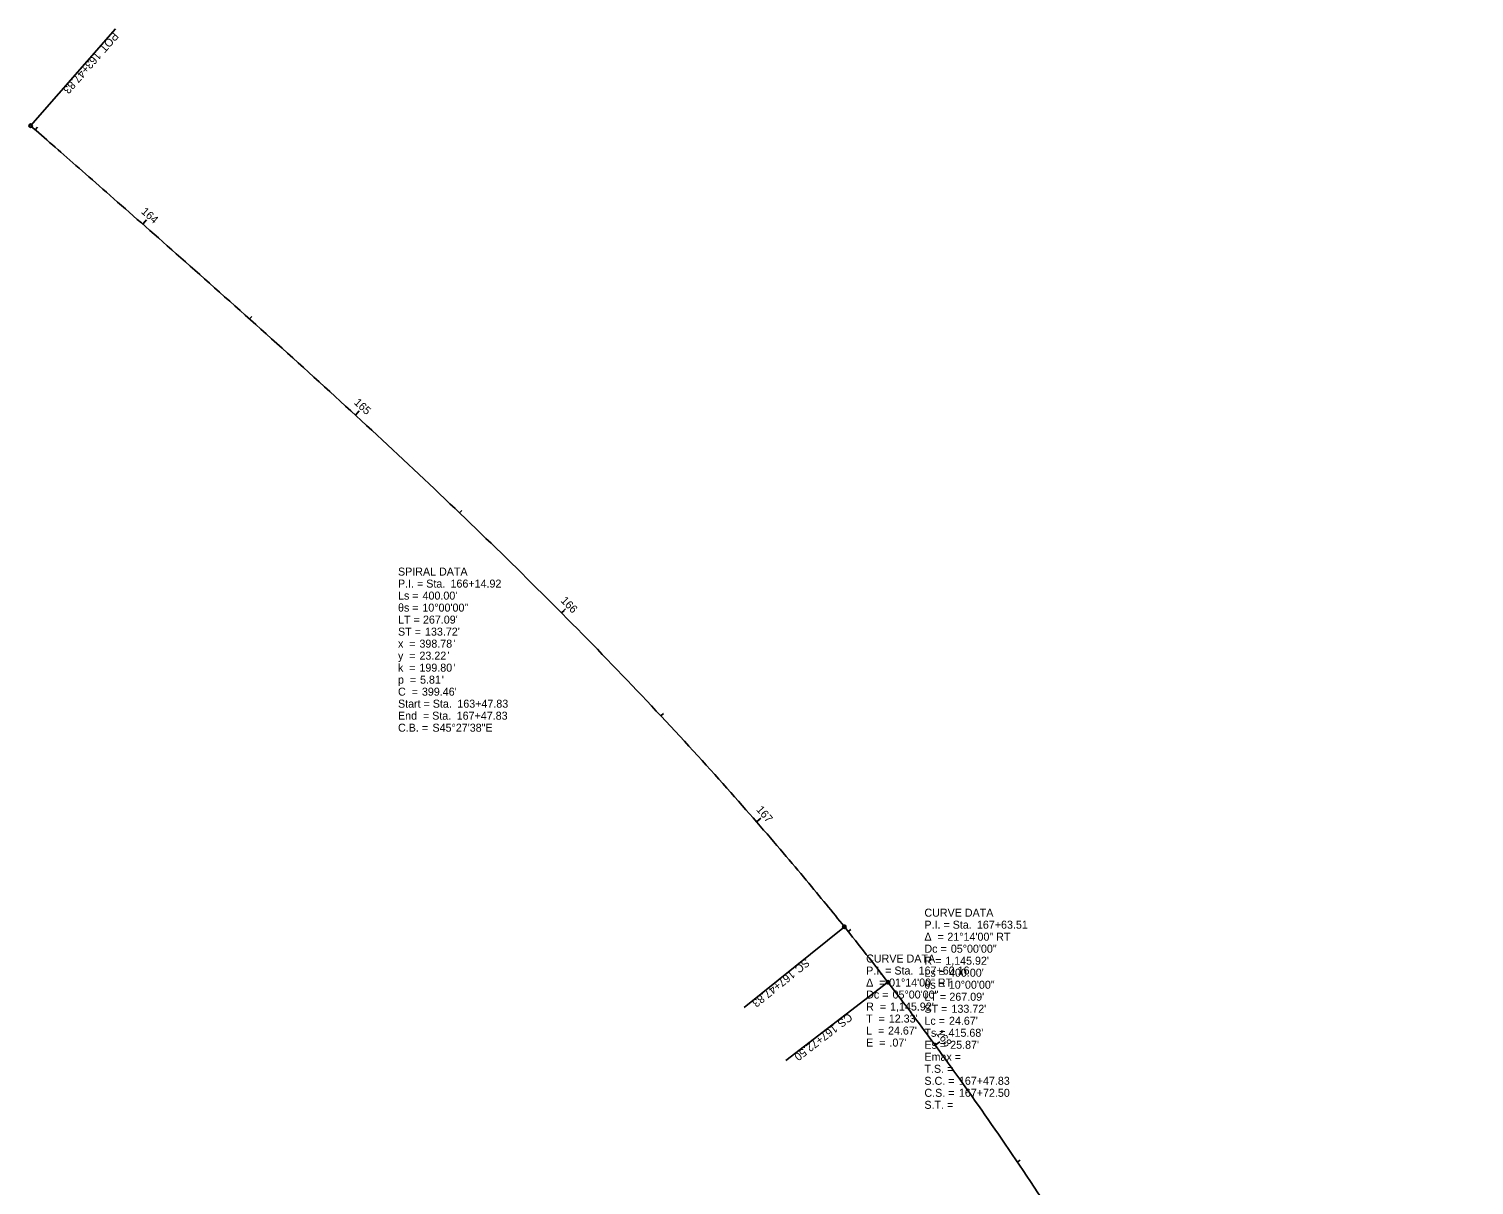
# Model space of a CAD drawing. Extents: x 2297881 to 2300632, y 559916 to 564460.
# Drawn here: x 2297881 to 2298386, y 564055 to 564460 of the extents above; entities that cross this region are included whole.
import ezdxf

# ---------------------------------------------------------------- set-up
doc = ezdxf.new("R2010")
doc.units = 0
for name, color, linetype in [('GE_X_Alignment', 7, 'Continuous'), ('GE_X_Alignment_1000_Cardinal_Points', 7, 'Continuous'), ('GE_X_Alignment_1000_Curve_Data', 7, 'Continuous'), ('GE_X_Alignment_1000_Stations', 7, 'Continuous'), ('GE_X_Alignment_100_Cardinal_Points', 7, 'Continuous'), ('GE_X_Alignment_100_Curve_Data', 7, 'Continuous'), ('GE_X_Alignment_100_Stations', 7, 'Continuous'), ('GE_X_Alignment_500_Cardinal_Points', 7, 'Continuous'), ('GE_X_Alignment_500_Curve_Data', 7, 'Continuous'), ('GE_X_Alignment_500_Stations', 7, 'Continuous')]:
    doc.layers.add(name, color=color, linetype=linetype)

msp = doc.modelspace()

# ---------------------------------------------------------------- linework, layer by layer
at = {"layer": 'GE_X_Alignment'}
msp.add_arc((2297272.8, 563427.61), 1145.92, 37.5598, 38.79314, dxfattribs=at)
for points in [[(2297881.22, 564425.72), (2297886.23, 564421.33), (2297896.26, 564412.54), (2297916.31, 564394.96), (2297941.31, 564372.91), (2297971.13, 564346.25), (2298000.66, 564319.27), (2298029.82, 564291.88), (2298058.49, 564263.99), (2298086.58, 564235.51), (2298113.96, 564206.34), (2298136.09, 564181.41), (2298153.32, 564161.05), (2298161.76, 564150.73), (2298165.94, 564145.54)], [(2298181.18, 564126.15), (2298185.25, 564120.86), (2298193.28, 564110.22), (2298209, 564088.68), (2298228.01, 564061.29), (2298249.89, 564027.8), (2298270.94, 563993.79), (2298291.28, 563959.34), (2298311.01, 563924.55), (2298330.26, 563889.48), (2298349.14, 563854.22), (2298364.66, 563824.72), (2298377.02, 563801.09), (2298383.19, 563789.27), (2298386.28, 563783.36)]]:
    msp.add_open_spline(points, degree=3, dxfattribs=at)
at = {"layer": 'GE_X_Alignment_1000_Cardinal_Points'}
for p, q in [((2297881.22, 564425.72), (2297910.86, 564459.57)), ((2298165.94, 564145.54), (2298130.86, 564117.35)), ((2298181.18, 564126.15), (2298145.51, 564098.72))]:
    msp.add_line(p, q, dxfattribs=at)
for centre in [(2297881.22, 564425.72), (2298165.94, 564145.54), (2298181.18, 564126.15)]:
    msp.add_circle(centre, 0.6, dxfattribs=at)
at = {"layer": 'GE_X_Alignment_1000_Stations'}
msp.add_line((2297994.85, 564324.51), (2297995.66, 564325.4), dxfattribs=at)
at = {"layer": 'GE_X_Alignment_100_Cardinal_Points'}
for p, q in [((2297881.22, 564425.72), (2297910.86, 564459.57)), ((2298165.94, 564145.54), (2298130.86, 564117.35)), ((2298181.18, 564126.15), (2298145.51, 564098.72))]:
    msp.add_line(p, q, dxfattribs=at)
for centre in [(2297881.22, 564425.72), (2298165.94, 564145.54), (2298181.18, 564126.15)]:
    msp.add_circle(centre, 0.6, dxfattribs=at)
at = {"layer": 'GE_X_Alignment_100_Stations'}
for p, q in [((2297882.85, 564424.29), (2297883.64, 564425.19)), ((2297920.43, 564391.31), (2297921.75, 564392.81)), ((2297957.83, 564358.12), (2297958.63, 564359.01)), ((2297994.85, 564324.51), (2297996.2, 564325.98)), ((2298031.31, 564290.3), (2298032.14, 564291.17)), ((2298067, 564255.29), (2298068.42, 564256.7)), ((2298101.72, 564219.31), (2298102.6, 564220.13)), ((2298135.23, 564182.21), (2298136.74, 564183.52)), ((2298167.3, 564143.85), (2298168.23, 564144.6)), ((2298197.69, 564104.15), (2298199.31, 564105.33)), ((2298226.45, 564063.26), (2298227.45, 564063.93))]:
    msp.add_line(p, q, dxfattribs=at)
at = {"layer": 'GE_X_Alignment_500_Cardinal_Points'}
for p, q in [((2297881.22, 564425.72), (2297910.86, 564459.57)), ((2298165.94, 564145.54), (2298130.86, 564117.35)), ((2298181.18, 564126.15), (2298145.51, 564098.72))]:
    msp.add_line(p, q, dxfattribs=at)
for centre in [(2297881.22, 564425.72), (2298165.94, 564145.54), (2298181.18, 564126.15)]:
    msp.add_circle(centre, 0.6, dxfattribs=at)
at = {"layer": 'GE_X_Alignment_500_Stations'}
for p, q in [((2297920.43, 564391.31), (2297921.22, 564392.21)), ((2297994.85, 564324.51), (2297996.2, 564325.98)), ((2298067, 564255.29), (2298067.85, 564256.13)), ((2298135.23, 564182.21), (2298136.14, 564183)), ((2298197.69, 564104.15), (2298198.66, 564104.86))]:
    msp.add_line(p, q, dxfattribs=at)

# ---------------------------------------------------------------- texts
at = {"layer": 'GE_X_Alignment_1000_Cardinal_Points'}
for s, rotation, p in [('POT', 228.7931, (2297910.15, 564458.69)), ('163+47.83', 228.7931, (2297904.13, 564451.82)), ('167+47.83', 218.7931, (2298147.29, 564130.49)), ('SC', 218.7931, (2298152.37, 564134.57)), ('CS', 217.5598, (2298167.4, 564115.49)), ('167+72.50', 217.5598, (2298162.23, 564111.51))]:
    msp.add_text(s, height=2.8, rotation=rotation, dxfattribs=at).set_placement(p)
at = {"layer": 'GE_X_Alignment_1000_Curve_Data'}
for s, p in [('SPIRAL DATA', (2298009.76, 564268.37)), ('P.I. = Sta. ', (2298009.76, 564264.17)), ('166+14.92', (2298028.13, 564264.17)), ('Ls = ', (2298009.76, 564259.97)), ("400.00'", (2298018.35, 564259.97)), ('θs = ', (2298009.76, 564255.77)), ('10°00\'00"', (2298018.29, 564255.77)), ('LT = ', (2298009.76, 564251.57)), ("267.09'", (2298018.49, 564251.57)), ('ST = ', (2298009.76, 564247.37)), ('398.78', (2298017.26, 564243.17)), ("133.72'", (2298019.21, 564247.37)), ("'", (2298029.22, 564243.17)), ('y  = ', (2298009.76, 564238.97)), ('x  = ', (2298009.76, 564243.17)), ('23.22', (2298017.26, 564238.97)), ("'", (2298027.04, 564238.97)), ('k  = ', (2298009.76, 564234.77)), ('199.80', (2298017.26, 564234.77)), ("'", (2298029.22, 564234.77)), ('p  = ', (2298009.76, 564230.57)), ('5.81', (2298017.47, 564230.57)), ("'", (2298025.08, 564230.57)), ('C  = ', (2298009.76, 564226.37)), ("399.46'", (2298018.13, 564226.37)), ('Start = Sta. ', (2298009.76, 564222.17)), ('End  = Sta. ', (2298009.76, 564217.97)), ('167+47.83', (2298030.3, 564217.97)), ('163+47.83', (2298030.52, 564222.17)), ('C.B. = ', (2298009.76, 564213.77)), ('S45°27\'38"E', (2298021.82, 564213.77)), ('CURVE DATA', (2298193.95, 564149.07)), ('P.I. = Sta. ', (2298193.95, 564144.87)), ('167+63.51', (2298212.32, 564144.87)), ('Δ  = ', (2298193.95, 564140.67)), ('21°14\'00" RT', (2298201.97, 564140.67)), ('CURVE DATA', (2298173.56, 564133.04)), ('Dc = ', (2298193.95, 564136.47)), ('R = ', (2298193.95, 564132.27)), ("1,145.92'", (2298201.23, 564132.27)), ('05°00\'00"', (2298203.19, 564136.47)), ('P.I. = Sta. ', (2298173.56, 564128.84)), ('167+60.16', (2298191.93, 564128.84)), ('Ls = ', (2298193.95, 564128.07)), ("400.00'", (2298202.54, 564128.07)), ('Δ  = ', (2298173.56, 564124.64)), ('01°14\'00" RT', (2298181.58, 564124.64)), ('θs = ', (2298193.95, 564123.87)), ('10°00\'00"', (2298202.48, 564123.87)), ('Dc = ', (2298173.56, 564120.44)), ('05°00\'00"', (2298182.8, 564120.44)), ('LT = ', (2298193.95, 564119.67)), ("267.09'", (2298202.68, 564119.67)), ('T  = ', (2298173.56, 564112.04)), ('R  = ', (2298173.56, 564116.24)), ("12.33'", (2298181.49, 564112.04)), ("1,145.92'", (2298181.93, 564116.24)), ('ST = ', (2298193.95, 564115.47)), ("133.72'", (2298203.41, 564115.47)), ('L  = ', (2298173.56, 564107.84)), ("24.67'", (2298181.21, 564107.84)), ('Ts = ', (2298193.95, 564107.07)), ('Lc = ', (2298193.95, 564111.27)), ("415.68'", (2298202.39, 564107.07)), ("24.67'", (2298202.54, 564111.27)), ('E  = ', (2298173.56, 564103.64)), (".07'", (2298181.71, 564103.64)), ('Es = ', (2298193.95, 564102.87)), ("25.87'", (2298202.97, 564102.87)), ('Emax = ', (2298193.95, 564098.67)), ('T.S. = ', (2298193.95, 564094.47)), ('S.C. = ', (2298193.95, 564090.27)), ('167+47.83', (2298206.01, 564090.27)), ('S.T. = ', (2298193.95, 564081.87)), ('C.S. = ', (2298193.95, 564086.07)), ('167+72.50', (2298206.01, 564086.07))]:
    msp.add_text(s, height=2.8, dxfattribs=at).set_placement(p)
at = {"layer": 'GE_X_Alignment_100_Cardinal_Points'}
for s, rotation, p in [('POT', 228.7931, (2297910.15, 564458.69)), ('163+47.83', 228.7931, (2297904.13, 564451.82)), ('167+47.83', 218.7931, (2298147.29, 564130.49)), ('SC', 218.7931, (2298152.37, 564134.57)), ('CS', 217.5598, (2298167.4, 564115.49)), ('167+72.50', 217.5598, (2298162.23, 564111.51))]:
    msp.add_text(s, height=2.8, rotation=rotation, dxfattribs=at).set_placement(p)
at = {"layer": 'GE_X_Alignment_100_Curve_Data'}
for s, p in [('SPIRAL DATA', (2298009.76, 564268.37)), ('P.I. = Sta. ', (2298009.76, 564264.17)), ('166+14.92', (2298028.13, 564264.17)), ('Ls = ', (2298009.76, 564259.97)), ("400.00'", (2298018.35, 564259.97)), ('θs = ', (2298009.76, 564255.77)), ('10°00\'00"', (2298018.29, 564255.77)), ('LT = ', (2298009.76, 564251.57)), ("267.09'", (2298018.49, 564251.57)), ('ST = ', (2298009.76, 564247.37)), ('398.78', (2298017.26, 564243.17)), ("133.72'", (2298019.21, 564247.37)), ("'", (2298029.22, 564243.17)), ('y  = ', (2298009.76, 564238.97)), ('x  = ', (2298009.76, 564243.17)), ('23.22', (2298017.26, 564238.97)), ("'", (2298027.04, 564238.97)), ('k  = ', (2298009.76, 564234.77)), ('199.80', (2298017.26, 564234.77)), ("'", (2298029.22, 564234.77)), ('p  = ', (2298009.76, 564230.57)), ('5.81', (2298017.47, 564230.57)), ("'", (2298025.08, 564230.57)), ('C  = ', (2298009.76, 564226.37)), ("399.46'", (2298018.13, 564226.37)), ('Start = Sta. ', (2298009.76, 564222.17)), ('End  = Sta. ', (2298009.76, 564217.97)), ('167+47.83', (2298030.3, 564217.97)), ('163+47.83', (2298030.52, 564222.17)), ('C.B. = ', (2298009.76, 564213.77)), ('S45°27\'38"E', (2298021.82, 564213.77)), ('CURVE DATA', (2298193.95, 564149.07)), ('P.I. = Sta. ', (2298193.95, 564144.87)), ('167+63.51', (2298212.32, 564144.87)), ('Δ  = ', (2298193.95, 564140.67)), ('21°14\'00" RT', (2298201.97, 564140.67)), ('CURVE DATA', (2298173.56, 564133.04)), ('Dc = ', (2298193.95, 564136.47)), ('R = ', (2298193.95, 564132.27)), ("1,145.92'", (2298201.23, 564132.27)), ('05°00\'00"', (2298203.19, 564136.47)), ('P.I. = Sta. ', (2298173.56, 564128.84)), ('167+60.16', (2298191.93, 564128.84)), ('Ls = ', (2298193.95, 564128.07)), ("400.00'", (2298202.54, 564128.07)), ('Δ  = ', (2298173.56, 564124.64)), ('01°14\'00" RT', (2298181.58, 564124.64)), ('θs = ', (2298193.95, 564123.87)), ('10°00\'00"', (2298202.48, 564123.87)), ('Dc = ', (2298173.56, 564120.44)), ('05°00\'00"', (2298182.8, 564120.44)), ('LT = ', (2298193.95, 564119.67)), ("267.09'", (2298202.68, 564119.67)), ('T  = ', (2298173.56, 564112.04)), ('R  = ', (2298173.56, 564116.24)), ("12.33'", (2298181.49, 564112.04)), ("1,145.92'", (2298181.93, 564116.24)), ('ST = ', (2298193.95, 564115.47)), ("133.72'", (2298203.41, 564115.47)), ('L  = ', (2298173.56, 564107.84)), ("24.67'", (2298181.21, 564107.84)), ('Ts = ', (2298193.95, 564107.07)), ('Lc = ', (2298193.95, 564111.27)), ("415.68'", (2298202.39, 564107.07)), ("24.67'", (2298202.54, 564111.27)), ('E  = ', (2298173.56, 564103.64)), (".07'", (2298181.71, 564103.64)), ('Es = ', (2298193.95, 564102.87)), ("25.87'", (2298202.97, 564102.87)), ('Emax = ', (2298193.95, 564098.67)), ('T.S. = ', (2298193.95, 564094.47)), ('S.C. = ', (2298193.95, 564090.27)), ('167+47.83', (2298206.01, 564090.27)), ('S.T. = ', (2298193.95, 564081.87)), ('C.S. = ', (2298193.95, 564086.07)), ('167+72.50', (2298206.01, 564086.07))]:
    msp.add_text(s, height=2.8, dxfattribs=at).set_placement(p)
at = {"layer": 'GE_X_Alignment_100_Stations'}
for s, rotation, p in [('164', 318.623, (2297919.68, 564395.36)), ('165', 317.3459, (2297994.15, 564328.62)), ('166', 314.8188, (2298066.49, 564259.41)), ('167', 311.0417, (2298134.96, 564186.4)), ('168', 306.2319, (2298197.81, 564108.3))]:
    msp.add_text(s, height=2.8, rotation=rotation, dxfattribs=at).set_placement(p)
at = {"layer": 'GE_X_Alignment_500_Cardinal_Points'}
for s, rotation, p in [('POT', 228.7931, (2297910.15, 564458.69)), ('163+47.83', 228.7931, (2297904.13, 564451.82)), ('167+47.83', 218.7931, (2298147.29, 564130.49)), ('SC', 218.7931, (2298152.37, 564134.57)), ('CS', 217.5598, (2298167.4, 564115.49)), ('167+72.50', 217.5598, (2298162.23, 564111.51))]:
    msp.add_text(s, height=2.8, rotation=rotation, dxfattribs=at).set_placement(p)
at = {"layer": 'GE_X_Alignment_500_Curve_Data'}
for s, p in [('SPIRAL DATA', (2298009.76, 564268.37)), ('P.I. = Sta. ', (2298009.76, 564264.17)), ('166+14.92', (2298028.13, 564264.17)), ('Ls = ', (2298009.76, 564259.97)), ("400.00'", (2298018.35, 564259.97)), ('θs = ', (2298009.76, 564255.77)), ('10°00\'00"', (2298018.29, 564255.77)), ('LT = ', (2298009.76, 564251.57)), ("267.09'", (2298018.49, 564251.57)), ('ST = ', (2298009.76, 564247.37)), ('398.78', (2298017.26, 564243.17)), ("133.72'", (2298019.21, 564247.37)), ("'", (2298029.22, 564243.17)), ('y  = ', (2298009.76, 564238.97)), ('x  = ', (2298009.76, 564243.17)), ('23.22', (2298017.26, 564238.97)), ("'", (2298027.04, 564238.97)), ('k  = ', (2298009.76, 564234.77)), ('199.80', (2298017.26, 564234.77)), ("'", (2298029.22, 564234.77)), ('p  = ', (2298009.76, 564230.57)), ('5.81', (2298017.47, 564230.57)), ("'", (2298025.08, 564230.57)), ('C  = ', (2298009.76, 564226.37)), ("399.46'", (2298018.13, 564226.37)), ('Start = Sta. ', (2298009.76, 564222.17)), ('End  = Sta. ', (2298009.76, 564217.97)), ('167+47.83', (2298030.3, 564217.97)), ('163+47.83', (2298030.52, 564222.17)), ('C.B. = ', (2298009.76, 564213.77)), ('S45°27\'38"E', (2298021.82, 564213.77)), ('CURVE DATA', (2298193.95, 564149.07)), ('P.I. = Sta. ', (2298193.95, 564144.87)), ('167+63.51', (2298212.32, 564144.87)), ('Δ  = ', (2298193.95, 564140.67)), ('21°14\'00" RT', (2298201.97, 564140.67)), ('CURVE DATA', (2298173.56, 564133.04)), ('Dc = ', (2298193.95, 564136.47)), ('R = ', (2298193.95, 564132.27)), ("1,145.92'", (2298201.23, 564132.27)), ('05°00\'00"', (2298203.19, 564136.47)), ('P.I. = Sta. ', (2298173.56, 564128.84)), ('167+60.16', (2298191.93, 564128.84)), ('Ls = ', (2298193.95, 564128.07)), ("400.00'", (2298202.54, 564128.07)), ('Δ  = ', (2298173.56, 564124.64)), ('01°14\'00" RT', (2298181.58, 564124.64)), ('θs = ', (2298193.95, 564123.87)), ('10°00\'00"', (2298202.48, 564123.87)), ('Dc = ', (2298173.56, 564120.44)), ('05°00\'00"', (2298182.8, 564120.44)), ('LT = ', (2298193.95, 564119.67)), ("267.09'", (2298202.68, 564119.67)), ('T  = ', (2298173.56, 564112.04)), ('R  = ', (2298173.56, 564116.24)), ("12.33'", (2298181.49, 564112.04)), ("1,145.92'", (2298181.93, 564116.24)), ('ST = ', (2298193.95, 564115.47)), ("133.72'", (2298203.41, 564115.47)), ('L  = ', (2298173.56, 564107.84)), ("24.67'", (2298181.21, 564107.84)), ('Ts = ', (2298193.95, 564107.07)), ('Lc = ', (2298193.95, 564111.27)), ("415.68'", (2298202.39, 564107.07)), ("24.67'", (2298202.54, 564111.27)), ('E  = ', (2298173.56, 564103.64)), (".07'", (2298181.71, 564103.64)), ('Es = ', (2298193.95, 564102.87)), ("25.87'", (2298202.97, 564102.87)), ('Emax = ', (2298193.95, 564098.67)), ('T.S. = ', (2298193.95, 564094.47)), ('S.C. = ', (2298193.95, 564090.27)), ('167+47.83', (2298206.01, 564090.27)), ('S.T. = ', (2298193.95, 564081.87)), ('C.S. = ', (2298193.95, 564086.07)), ('167+72.50', (2298206.01, 564086.07))]:
    msp.add_text(s, height=2.8, dxfattribs=at).set_placement(p)
at = {"layer": 'GE_X_Alignment_500_Stations'}
msp.add_text('165', height=2.8, rotation=317.3459, dxfattribs=at).set_placement((2297994.15, 564328.62))

doc.saveas('drawing.dxf')
